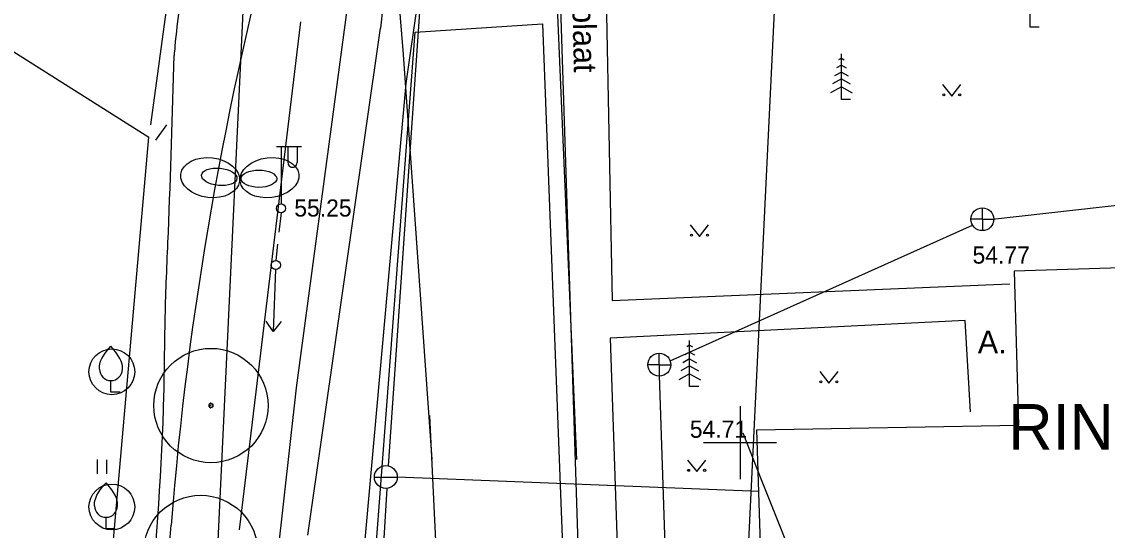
# Model space of a CAD drawing. Extents: x 9156 to 9809, y 2728 to 4000.
# Drawn here: x 9518.57 to 9566.07, y 3646.17 to 3668.39 of the extents above; entities that cross this region are included whole.
import ezdxf

# ---------------------------------------------------------------- set-up
doc = ezdxf.new("R2010")
doc.units = 0
for name, color, linetype in [('Level 1', 7, 'Continuous'), ('Level 16', 7, 'Continuous'), ('Level 17', 7, 'Continuous'), ('Level 18', 7, 'Continuous'), ('Level 21', 7, 'Continuous'), ('Level 5', 7, 'Continuous'), ('Level 54', 7, 'Continuous'), ('Level 56', 7, 'Continuous'), ('Level 58', 7, 'Continuous'), ('Level 7', 7, 'Continuous'), ('Level 8', 7, 'Continuous'), ('Level 9', 7, 'Continuous')]:
    doc.layers.add(name, color=color, linetype=linetype)

# ---------------------------------------------------------------- blocks, each defined once
blk = doc.blocks.new('KKOL')
at = {"layer": 'Level 58'}
for p, q in [((0, 1.59349), (0, -1.5935)), ((-1.5935, 0), (1.59349, 0))]:
    blk.add_line(p, q, dxfattribs=at)

msp = doc.modelspace()

# ---------------------------------------------------------------- linework, layer by layer
at = {"layer": 'Level 1'}
msp.add_line((9552.269, 3685.137), (9546.632, 3567.879), dxfattribs=at)
msp.add_line((9552.269, 3685.137), (9546.632, 3567.879), dxfattribs=at)
at = {"layer": 'Level 16'}
for p, q in [((9530.595, 3652.391), (9533.162, 3671.517)), ((9528.027, 3629.73), (9530.595, 3652.391))]:
    msp.add_line(p, q, dxfattribs=at)
at = {"layer": 'Level 17'}
for p, q in [((9528.098, 3646.188), (9530.78, 3668.394)), ((9531.089, 3645.951), (9534.27, 3668.117))]:
    msp.add_line(p, q, dxfattribs=at)
msp.add_arc((9552.794, 3666.647), 18.583, 87.0536, 175.4633, dxfattribs=at)
at = {"layer": 'Level 18'}
for p, q in [((9535.778, 3667.939), (9541.349, 3668.295)), ((9541.349, 3668.295), (9545.183, 3569.878)), ((9533.165, 3633.502), (9535.778, 3667.939))]:
    msp.add_line(p, q, dxfattribs=at)
for centre, radius, start, end in [((9674.033, 3634.527), 149.4, 164.76358, 175.44602), ((9404.886, 3655.965), 120.6, 323.52136, 355.44602)]:
    msp.add_arc(centre, radius, start, end, dxfattribs=at)
at = {"layer": 'Level 21'}
for centre in [(9522.513, 3653.095), (9522.513, 3647.187)]:
    msp.add_circle(centre, 1, dxfattribs=at)
at = {"layer": 'Level 54'}
for p, q in [((9530.197, 3710.192), (9525.746, 3615.921)), ((9538.67, 3707.573), (9534.596, 3648.984)), ((9543.675, 3692.045), (9544.407, 3656.208)), ((9533.878, 3683.802), (9535.259, 3666.96)), ((9526.074, 3677.818), (9524.211, 3663.894)), ((9541.865, 3677.837), (9545.509, 3564.357)), ((9562.691, 3668.162), (9562.691, 3670.162)), ((9563.091, 3668.162), (9562.691, 3668.162)), ((9517.334, 3667.641), (9524.138, 3663.351)), ((9535.259, 3666.96), (9536.512, 3649.259)), ((9554.435, 3664.996), (9554.435, 3666.996)), ((9554.435, 3666.496), (9554.223, 3666.378)), ((9554.435, 3666.796), (9554.309, 3666.726)), ((9554.435, 3666.796), (9554.561, 3666.726)), ((9554.435, 3666.496), (9554.647, 3666.378)), ((9554.435, 3666.196), (9554.137, 3666.03)), ((9554.435, 3666.196), (9554.733, 3666.03)), ((9554.435, 3665.546), (9553.96, 3665.281)), ((9554.435, 3665.896), (9554.051, 3665.682)), ((9554.435, 3665.896), (9554.819, 3665.682)), ((9554.435, 3665.546), (9554.91, 3665.281)), ((9558.861, 3665.646), (9559.264, 3665.141)), ((9559.264, 3665.141), (9559.661, 3665.646)), ((9554.835, 3664.996), (9554.435, 3664.996)), ((9524.911, 3663.885), (9524.416, 3663.224)), ((9518.529, 3600.046), (9524.138, 3663.351)), ((9529.717, 3662.935), (9530.817, 3662.935)), ((9529.917, 3662.935), (9529.917, 3660.435)), ((9530.217, 3662.935), (9530.217, 3662.235)), ((9530.617, 3662.935), (9530.617, 3662.235)), ((9561.05, 3659.763), (9575.986, 3661.444)), ((9560.601, 3659.763), (9560.601, 3660.263)), ((9661.889, 3660.444), (9561.995, 3657.498)), ((9529.917, 3660.035), (9529.824, 3659.199)), ((9560.601, 3659.763), (9560.101, 3659.763)), ((9560.601, 3659.763), (9561.101, 3659.763)), ((9560.601, 3659.763), (9560.601, 3659.263)), ((9546.935, 3653.574), (9560.175, 3659.502)), ((9547.821, 3659.515), (9548.224, 3659.01)), ((9548.224, 3659.01), (9548.621, 3659.515)), ((9529.766, 3658.675), (9529.687, 3657.959)), ((9529.679, 3657.56), (9529.571, 3654.862)), ((9561.995, 3657.498), (9562.18, 3650.758)), ((9544.407, 3656.208), (9561.807, 3656.94)), ((9529.571, 3654.862), (9529.258, 3655.314)), ((9529.919, 3655.287), (9529.571, 3654.862)), ((9559.843, 3655.333), (9544.314, 3654.566)), ((9560.082, 3651.352), (9559.843, 3655.333)), ((9544.314, 3654.566), (9547.393, 3564.619)), ((9547.793, 3654.257), (9547.667, 3654.187)), ((9547.793, 3652.457), (9547.793, 3654.457)), ((9547.793, 3654.257), (9547.919, 3654.187)), ((9546.465, 3653.404), (9546.465, 3653.904)), ((9547.793, 3653.657), (9547.495, 3653.491)), ((9547.793, 3653.957), (9547.581, 3653.839)), ((9547.793, 3653.957), (9548.005, 3653.839)), ((9547.793, 3653.657), (9548.091, 3653.491)), ((9546.465, 3653.404), (9545.965, 3653.404)), ((9546.465, 3653.404), (9546.965, 3653.404)), ((9546.465, 3653.404), (9546.465, 3652.904)), ((9547.793, 3653.357), (9547.409, 3653.144)), ((9547.793, 3653.357), (9548.177, 3653.144)), ((9553.488, 3653.106), (9553.891, 3652.601)), ((9553.891, 3652.601), (9554.288, 3653.106)), ((9522.472, 3652.211), (9522.472, 3652.711)), ((9522.472, 3652.211), (9522.472, 3652.711)), ((9546.465, 3652.931), (9547.404, 3623.728)), ((9547.793, 3653.007), (9547.317, 3652.743)), ((9547.793, 3653.007), (9548.268, 3652.743)), ((9522.872, 3652.211), (9522.472, 3652.211)), ((9522.872, 3652.211), (9522.472, 3652.211)), ((9548.193, 3652.457), (9547.793, 3652.457)), ((9550, 3651.25), (9550, 3648.75)), ((9536.853, 3642.38), (9536.432, 3651.179)), ((9550.727, 3650.558), (9562.18, 3650.758)), ((9553.951, 3553.575), (9550.727, 3650.558)), ((9548.75, 3650), (9551.25, 3650)), ((9521.87, 3649.258), (9521.87, 3648.638)), ((9522.276, 3649.247), (9522.276, 3648.638)), ((9547.7, 3649.238), (9548.103, 3648.733)), ((9548.103, 3648.733), (9548.5, 3649.238)), ((9534, 3648.493), (9535, 3648.493)), ((9535, 3648.499), (9550.816, 3647.878)), ((9534.55, 3647.996), (9531.162, 3595.485)), ((9522.259, 3646.235), (9522.259, 3646.735)), ((9522.259, 3646.235), (9522.259, 3646.735)), ((9522.659, 3646.235), (9522.259, 3646.235)), ((9522.659, 3646.235), (9522.259, 3646.235))]:
    msp.add_line(p, q, dxfattribs=at)
for points in [[(9541.616, 3677.918), (9542.847, 3649.259)], [(9521.972, 3653.211), (9521.972, 3653.361), (9521.982, 3653.427), (9522.019, 3653.555), (9522.076, 3653.679), (9522.222, 3653.911), (9522.382, 3654.116), (9522.472, 3654.211)], [(9521.972, 3653.211), (9521.972, 3653.361), (9521.982, 3653.427), (9522.019, 3653.555), (9522.076, 3653.679), (9522.222, 3653.911), (9522.382, 3654.116), (9522.472, 3654.211)], [(9522.972, 3653.211), (9522.972, 3653.361), (9522.962, 3653.427), (9522.925, 3653.555), (9522.868, 3653.679), (9522.722, 3653.911), (9522.562, 3654.116), (9522.472, 3654.211)], [(9522.972, 3653.211), (9522.972, 3653.361), (9522.962, 3653.427), (9522.925, 3653.555), (9522.868, 3653.679), (9522.722, 3653.911), (9522.562, 3654.116), (9522.472, 3654.211)], [(9521.759, 3647.235), (9521.759, 3647.385), (9521.769, 3647.45), (9521.806, 3647.578), (9521.862, 3647.702), (9522.009, 3647.935), (9522.169, 3648.139), (9522.259, 3648.235)], [(9521.759, 3647.235), (9521.759, 3647.385), (9521.769, 3647.45), (9521.806, 3647.578), (9521.862, 3647.702), (9522.009, 3647.935), (9522.169, 3648.139), (9522.259, 3648.235)], [(9522.759, 3647.235), (9522.759, 3647.385), (9522.749, 3647.45), (9522.711, 3647.578), (9522.655, 3647.702), (9522.509, 3647.935), (9522.349, 3648.139), (9522.259, 3648.235)], [(9522.759, 3647.235), (9522.759, 3647.385), (9522.749, 3647.45), (9522.711, 3647.578), (9522.655, 3647.702), (9522.509, 3647.935), (9522.349, 3648.139), (9522.259, 3648.235)]]:
    msp.add_lwpolyline(points, dxfattribs=at)
for centre, radius in [((9558.911, 3665.196), 0.0428), ((9559.611, 3665.196), 0.0452), ((9529.917, 3660.235), 0.2), ((9560.601, 3659.763), 0.5), ((9547.871, 3659.065), 0.0428), ((9548.571, 3659.065), 0.0452), ((9529.687, 3657.759), 0.199), ((9546.465, 3653.404), 0.5), ((9553.538, 3652.656), 0.0428), ((9554.238, 3652.656), 0.0452), ((9534.5, 3648.493), 0.5), ((9547.75, 3648.788), 0.0428), ((9548.45, 3648.788), 0.0452)]:
    msp.add_circle(centre, radius, dxfattribs=at)
for centre, radius, start, end in [((9530.417, 3662.235), 0.2, 179.9393, 0.0607), ((9522.472, 3653.211), 0.5, 180, 0), ((9522.472, 3653.211), 0.5, 180, 0), ((9522.259, 3647.235), 0.5, 180, 0), ((9522.259, 3647.235), 0.5, 180, 0)]:
    msp.add_arc(centre, radius, start, end, dxfattribs=at)
for points in [[(9527.262, 3685.588), (9526.61, 3682.693), (9526.291, 3679.117), (9525.717, 3670.817), (9525.27, 3667.306), (9525.238, 3666.919)], [(9538.06, 3594.642), (9536.329, 3593.597), (9534.047, 3593.075), (9532.091, 3592.553), (9529.613, 3592.814), (9527.787, 3593.923), (9525.961, 3595.685), (9524.918, 3597.382), (9522.701, 3599.405), (9521.07, 3601.558), (9520.744, 3604.755), (9521.462, 3607.235), (9521.331, 3610.302), (9521.657, 3614.217), (9522.246, 3618.832), (9522.963, 3622.29), (9523.224, 3624.639), (9522.898, 3626.727), (9523.811, 3635.059), (9523.942, 3638.583), (9524.202, 3642.563), (9524.79, 3652.067), (9524.855, 3655.721), (9524.985, 3659.18), (9525.238, 3666.92)], [(9551.163, 3554.03), (9551.63, 3553.617), (9552.412, 3553.356), (9553.456, 3553.552), (9550.134, 3650.407)]]:
    msp.add_spline(points, degree=3, dxfattribs=at)
at = {"layer": 'Level 56'}
for p, q in [((9528.098, 3646.188), (9530.78, 3668.394)), ((9535.778, 3667.939), (9541.349, 3668.295)), ((9541.349, 3668.295), (9545.183, 3569.878)), ((9531.089, 3645.951), (9534.27, 3668.117)), ((9533.165, 3633.502), (9535.778, 3667.939))]:
    msp.add_line(p, q, dxfattribs=at)
for centre, radius, start, end in [((9552.794, 3666.647), 18.583, 87.0536, 175.4633), ((9674.033, 3634.527), 149.4, 164.76358, 175.44602), ((9404.886, 3655.965), 120.6, 323.52136, 355.44602)]:
    msp.add_arc(centre, radius, start, end, dxfattribs=at)
at = {"layer": 'Level 7'}
for p, q in [((9536.573, 3674.198), (9535.382, 3665.696)), ((9535.382, 3665.696), (9532.485, 3633.588))]:
    msp.add_line(p, q, dxfattribs=at)
at = {"layer": 'Level 8'}
for centre, major_axis, ratio in [((9526.816, 3661.579), (1.285, -0.15), 0.674652), ((9526.816, 3661.579), (1.285, -0.15), 0.674652), ((9526.816, 3661.579), (1.285, -0.15), 0.674652), ((9526.816, 3661.579), (1.285, -0.15), 0.674652), ((9529.408, 3661.579), (-1.285, -0.15), 0.674652), ((9529.408, 3661.579), (-1.285, -0.15), 0.674652), ((9529.408, 3661.579), (-1.285, -0.15), 0.674652), ((9529.408, 3661.579), (-1.285, -0.15), 0.674652), ((9527.211, 3661.615), (0.774, -0.072), 0.486914), ((9527.211, 3661.615), (0.774, -0.072), 0.486914), ((9527.211, 3661.615), (0.774, -0.072), 0.486914), ((9527.211, 3661.615), (0.774, -0.072), 0.486914), ((9528.948, 3661.535), (-0.778, 0.002), 0.486914), ((9528.948, 3661.535), (-0.778, 0.002), 0.486914), ((9528.948, 3661.535), (-0.778, 0.002), 0.486914), ((9528.948, 3661.535), (-0.778, 0.002), 0.486914)]:
    msp.add_ellipse(centre, major_axis=major_axis, ratio=ratio, dxfattribs=at)
at = {"layer": 'Level 9'}
for p, q in [((9526.79, 3651.672), (9526.773, 3651.686)), ((9526.794, 3651.705), (9526.806, 3651.686)), ((9526.827, 3651.696), (9526.821, 3651.717)), ((9526.849, 3651.721), (9526.849, 3651.699)), ((9526.87, 3651.696), (9526.876, 3651.717)), ((9526.903, 3651.705), (9526.892, 3651.686)), ((9526.908, 3651.672), (9526.925, 3651.686)), ((9526.771, 3651.632), (9526.749, 3651.635)), ((9526.749, 3651.606), (9526.771, 3651.61)), ((9526.757, 3651.662), (9526.778, 3651.654)), ((9526.777, 3651.588), (9526.758, 3651.578)), ((9526.773, 3651.555), (9526.789, 3651.569)), ((9526.806, 3651.554), (9526.794, 3651.536)), ((9526.82, 3651.524), (9526.826, 3651.545)), ((9526.859, 3651.619), (9526.838, 3651.619)), ((9526.849, 3651.541), (9526.848, 3651.52)), ((9526.849, 3651.609), (9526.849, 3651.63)), ((9526.877, 3651.524), (9526.871, 3651.545)), ((9526.891, 3651.554), (9526.903, 3651.535)), ((9526.926, 3651.555), (9526.909, 3651.57)), ((9526.94, 3651.662), (9526.921, 3651.652)), ((9526.921, 3651.588), (9526.941, 3651.579)), ((9526.927, 3651.631), (9526.948, 3651.635)), ((9526.949, 3651.607), (9526.927, 3651.61))]:
    msp.add_line(p, q, dxfattribs=at)
for centre in [(9526.849, 3651.619), (9526.401, 3645.2)]:
    msp.add_circle(centre, 2.5, dxfattribs=at)
for radius, start, end in [(0.101, 122.8434, 139.0222), (0.0788, 138.6432, 154.5795), (0.0788, 105.9559, 123.0564), (0.101, 90.0356, 106.342), (0.0788, 74.31, 90.043), (0.101, 57.6108, 74.1981), (0.0788, 41.2062, 56.7795), (0.101, 24.5394, 40.9852), (0.101, 155.3123, 171.7042), (0.101, 187.9671, 204.8625), (0.0788, 171.5431, 187.6203), (0.101, 220.7122, 237.1166), (0.0788, 204.4529, 220.4774), (0.0788, 237.451, 253.0843), (0.101, 253.2952, 269.5718), (0.0788, 269.9461, 286.3473), (0.101, 285.972, 302.5562), (0.0788, 302.254, 320.086), (0.0788, 8.0619, 24.0332), (0.0788, 336.0557, 352.7558), (0.101, 319.7777, 336.0738), (0.101, 352.27, 8.583)]:
    msp.add_arc((9526.849, 3651.62), radius, start, end, dxfattribs=at)

# ---------------------------------------------------------------- block references
at = {"layer": 'Level 54'}
msp.add_blockref('KKOL', (9550, 3650), dxfattribs=at)

# ---------------------------------------------------------------- texts
at = {"layer": 'Level 5'}
msp.add_text('RINGTEE 1', height=2, dxfattribs=at).set_placement((9561.742, 3649.685))
at = {"layer": 'Level 54'}
msp.add_text('bet. plaat', height=1, rotation=271.2586, dxfattribs=at).set_placement((9542.609, 3671.667))
for s, height, p in [('55.25', 0.75, (9530.495, 3659.878)), ('54.77', 0.75, (9560.17, 3657.822)), ('A.', 1, (9560.403, 3653.898)), ('54.71', 0.75, (9547.8, 3650.212))]:
    msp.add_text(s, height=height, dxfattribs=at).set_placement(p)

doc.saveas('drawing.dxf')
